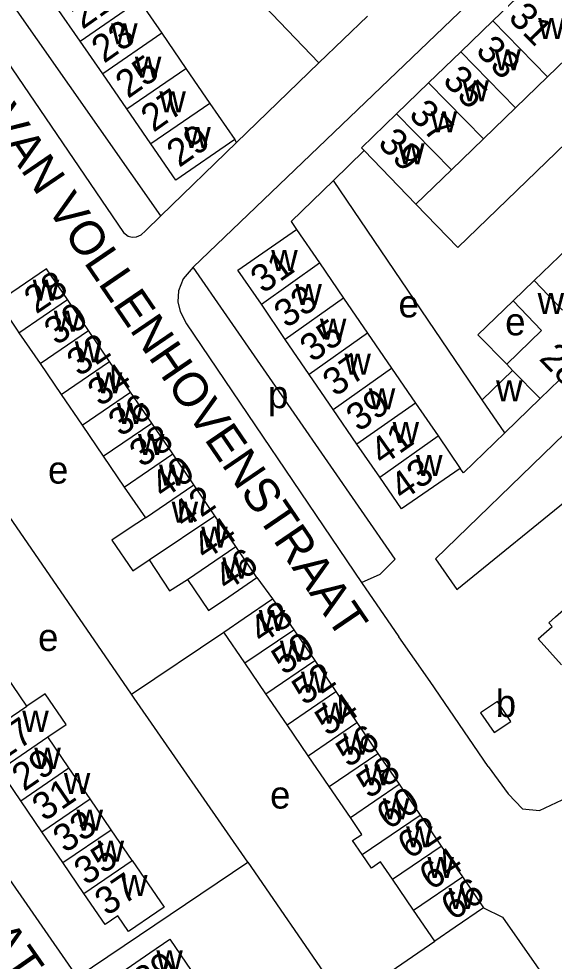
# Model space of a CAD drawing. Extents: x 157569 to 159501, y 382907 to 384670.
# Drawn here: x 158245.2 to 158323.4, y 383803.3 to 383940.8 of the extents above; entities that cross this region are included whole.
import ezdxf

# ---------------------------------------------------------------- set-up
doc = ezdxf.new("R2010")
doc.units = 0
for name, color, linetype in [('BLT_Basislijn', 7, 'Continuous'), ('BLT_Bebouwing', 7, 'Continuous'), ('BLT_Centroide', 7, 'Continuous'), ('BLT_Huisnummer', 7, 'Continuous'), ('BLT_Huisnummer_ tussenligend', 7, 'Continuous'), ('BLT_Onderverdeling_panden', 7, 'Continuous'), ('BLT_Straatnaam', 7, 'Continuous')]:
    doc.layers.add(name, color=color, linetype=linetype)

msp = doc.modelspace()

# ---------------------------------------------------------------- linework, layer by layer
at = {"layer": 'BLT_Basislijn'}
for p, q in [((158265.95, 383912.08), (158220.5, 383977.05)), ((158261.03, 383963.65), (158289.03, 383934.4)), ((158359.94, 383956.53), (158309.3, 383907.45)), ((158270.69, 383904.61), (158313.18, 383945.33)), ((158296.12, 383941.25), (158289.03, 383934.4)), ((158277.01, 383922.81), (158265.95, 383912.08)), ((158291.14, 383917.27), (158295.65, 383921.61)), ((158312.85, 383885.25), (158291.14, 383917.27)), ((158333.76, 383915.53), (158320.42, 383902.64)), ((158309.3, 383907.45), (158303.17, 383913.81)), ((158265.95, 383912.08), (158263.72, 383909.92)), ((158317.36, 383899.68), (158312.24, 383894.74)), ((158312.24, 383894.74), (158316.43, 383890.44)), ((158309.18, 383857.56), (158347.25, 383888.59)), ((158261.67, 383842.28), (158243.3, 383869.04)), ((158279.99, 383859.32), (158282.27, 383856.2)), ((158295.25, 383858.59), (158300.69, 383850.64)), ((158261.67, 383842.28), (158275.15, 383851.34)), ((158305.27, 383844.14), (158300.69, 383850.64)), ((158313.75, 383831.7), (158305.27, 383844.14)), ((158318.74, 383825.56), (158316.63, 383827.74)), ((158253.74, 383800.97), (158278.65, 383817.74)), ((158278.65, 383817.74), (158292.79, 383797.22)), ((158292.79, 383797.22), (158305.93, 383806.23))]:
    msp.add_line(p, q, dxfattribs=at)
for points in [[(158220.5, 383977.05), (158218.89, 383974.99), (158218.63, 383973.43), (158218.85, 383971.66), (158219.87, 383969.38), (158260.5, 383909.68), (158261.19, 383909.11), (158261.77, 383908.99), (158262.42, 383909.01), (158263.1, 383909.3), (158263.72, 383909.92)], [(158289.03, 383934.4), (158277.01, 383922.81)], [(158277.01, 383922.81), (158276.74, 383923.21)], [(158291.14, 383917.27), (158284.96, 383911.28), (158285.76, 383910.11)], [(158270.69, 383904.61), (158269.21, 383902.92), (158268.52, 383901.17), (158268.45, 383899.56), (158268.76, 383898.11), (158269.7, 383896.32), (158295.25, 383858.59)], [(158295.25, 383858.59), (158297.99, 383859.79), (158300.14, 383861.97), (158270.69, 383904.61)], [(158340.56, 383895.5), (158306.05, 383862.05), (158309.18, 383857.56)], [(158316.15, 383880.43), (158310.11, 383874.57), (158309.66, 383875.23)], [(158318.74, 383825.56), (158321.24, 383825.28), (158324.51, 383826.85), (158332.42, 383833.63), (158365.06, 383863.02)], [(158218.79, 383851.78), (158230.42, 383834.52), (158253.74, 383800.97)], [(158278.65, 383817.74), (158262.08, 383841.69), (158261.67, 383842.28)], [(158313.75, 383831.7), (158316.63, 383827.74)], [(158313.04, 383811.09), (158315.83, 383809.75), (158323.28, 383799.09)]]:
    msp.add_lwpolyline(points, dxfattribs=at)
at = {"layer": 'BLT_Bebouwing'}
for p, q in [((158314.39, 383940.55), (158318.93, 383944.94)), ((158262.81, 383943.51), (158266.09, 383938.73)), ((158254.2, 383937.59), (158250.71, 383942.57)), ((158309.72, 383936.03), (158314.39, 383940.55)), ((158266.09, 383938.73), (158269.6, 383933.62)), ((158257.5, 383932.82), (158254.2, 383937.59)), ((158328.48, 383938.27), (158322.39, 383932.38)), ((158305.04, 383931.51), (158309.72, 383936.03)), ((158269.6, 383933.62), (158273.11, 383928.51)), ((158261.01, 383927.71), (158257.5, 383932.82)), ((158322.39, 383932.38), (158317.72, 383927.86)), ((158300.37, 383927), (158305.04, 383931.51)), ((158264.51, 383922.6), (158261.01, 383927.71)), ((158273.11, 383928.51), (158276.74, 383923.21)), ((158317.72, 383927.86), (158313.04, 383923.35)), ((158268.15, 383917.31), (158264.51, 383922.6)), ((158276.74, 383923.21), (158268.15, 383917.31)), ((158313.04, 383923.35), (158308.37, 383918.83)), ((158303.17, 383913.81), (158295.65, 383921.61)), ((158308.37, 383918.83), (158303.17, 383913.81)), ((158277.17, 383904.15), (158285.76, 383910.11)), ((158285.76, 383910.11), (158289.12, 383905.21)), ((158289.12, 383905.21), (158292.63, 383900.09)), ((158280.63, 383899.21), (158277.17, 383904.15)), ((158317.36, 383899.68), (158320.42, 383902.64)), ((158320.42, 383902.64), (158324.59, 383898.34)), ((158255.4, 383895.36), (158252.33, 383899.86)), ((158284.09, 383894.06), (158280.63, 383899.21)), ((158292.63, 383900.09), (158296.13, 383894.97)), ((158321.53, 383895.37), (158317.36, 383899.68)), ((158245.25, 383895.04), (158248.33, 383890.53)), ((158258.48, 383890.85), (158255.4, 383895.36)), ((158296.13, 383894.97), (158299.63, 383889.86)), ((158316.43, 383890.44), (158321.53, 383895.37)), ((158287.59, 383888.94), (158284.09, 383894.06)), ((158248.33, 383890.53), (158251.4, 383886.03)), ((158261.55, 383886.35), (158258.48, 383890.85)), ((158299.63, 383889.86), (158303.14, 383884.74)), ((158312.85, 383885.25), (158317.29, 383889.54)), ((158317.29, 383889.54), (158316.43, 383890.44)), ((158291.11, 383883.84), (158287.59, 383888.94)), ((158324.15, 383888.18), (158321.3, 383885.42)), ((158251.4, 383886.03), (158254.48, 383881.52)), ((158264.62, 383881.84), (158261.55, 383886.35)), ((158316.15, 383880.43), (158312.85, 383885.25)), ((158321.3, 383885.42), (158316.15, 383880.43)), ((158294.58, 383878.79), (158291.11, 383883.84)), ((158303.14, 383884.74), (158306.42, 383879.96)), ((158254.48, 383881.52), (158257.55, 383877.02)), ((158267.7, 383877.34), (158264.62, 383881.84)), ((158306.42, 383879.96), (158309.66, 383875.23)), ((158297.9, 383873.95), (158294.58, 383878.79)), ((158257.55, 383877.02), (158260.62, 383872.51)), ((158270.77, 383872.83), (158267.7, 383877.34)), ((158309.66, 383875.23), (158301.07, 383869.34)), ((158273.85, 383868.33), (158270.77, 383872.83)), ((158301.07, 383869.34), (158297.9, 383873.95)), ((158260.62, 383872.51), (158263.7, 383868.01)), ((158276.92, 383863.82), (158273.85, 383868.33)), ((158279.99, 383859.32), (158276.92, 383863.82)), ((158282.27, 383856.2), (158285.35, 383851.68)), ((158278.23, 383846.83), (158275.15, 383851.34)), ((158285.35, 383851.68), (158288.42, 383847.18)), ((158321.05, 383850.36), (158324.42, 383846.54)), ((158281.3, 383842.32), (158278.23, 383846.83)), ((158288.42, 383847.18), (158291.5, 383842.66)), ((158246.39, 383840.54), (158243.32, 383845.05)), ((158291.5, 383842.66), (158294.58, 383838.15)), ((158284.38, 383837.81), (158281.3, 383842.32)), ((158287.46, 383833.3), (158284.38, 383837.81)), ((158294.58, 383838.15), (158297.65, 383833.64)), ((158252.55, 383831.52), (158249.47, 383836.03)), ((158290.54, 383828.79), (158287.46, 383833.3)), ((158297.65, 383833.64), (158300.73, 383829.13)), ((158245.51, 383826.72), (158242.43, 383831.23)), ((158293.62, 383824.28), (158290.54, 383828.79)), ((158300.73, 383829.13), (158303.81, 383824.62)), ((158248.59, 383822.2), (158245.51, 383826.72)), ((158258.7, 383822.49), (158255.63, 383827)), ((158303.81, 383824.62), (158306.89, 383820.11)), ((158251.67, 383817.69), (158248.59, 383822.2)), ((158261.78, 383817.98), (158258.7, 383822.49)), ((158306.89, 383820.11), (158309.96, 383815.6)), ((158254.74, 383813.18), (158251.67, 383817.69)), ((158302.85, 383810.75), (158299.77, 383815.26)), ((158309.96, 383815.6), (158313.04, 383811.09)), ((158305.93, 383806.23), (158302.85, 383810.75))]:
    msp.add_line(p, q, dxfattribs=at)
for points in [[(158295.65, 383921.61), (158295.24, 383922.04), (158300.37, 383927)], [(158252.33, 383899.86), (158249.25, 383904.37), (158242.18, 383899.54)], [(158242.18, 383899.54), (158245, 383895.41), (158245.25, 383895.04)], [(158321.05, 383850.36), (158323.07, 383852.14), (158322.58, 383852.7), (158323.57, 383853.57), (158349.57, 383876.4), (158353.24, 383872.18), (158353.54, 383872.43)], [(158263.7, 383868.01), (158261.19, 383866.36), (158258.82, 383864.74), (158261.88, 383860.26), (158264.25, 383861.88)], [(158264.25, 383861.88), (158267.22, 383857.35), (158269.85, 383859)], [(158269.85, 383859), (158272.92, 383854.49), (158275.87, 383856.5), (158279.99, 383859.32)], [(158275.15, 383851.34), (158278.14, 383853.38), (158282.27, 383856.2)], [(158249.47, 383836.03), (158252.13, 383837.84), (158249.07, 383842.33), (158246.39, 383840.54)], [(158255.63, 383827), (158252.55, 383831.52)], [(158295.32, 383818.9), (158293.95, 383820.91), (158295.29, 383821.82), (158293.62, 383824.28)], [(158261.78, 383817.98), (158266.42, 383811.17), (158265.39, 383810.47), (158261.26, 383807.65), (158259.7, 383809.94), (158257.82, 383808.66), (158254.74, 383813.18)], [(158299.77, 383815.26), (158298.03, 383817.8), (158296.69, 383816.89), (158295.32, 383818.9)], [(158313.04, 383811.09), (158308.92, 383808.27), (158305.93, 383806.23)], [(158263.35, 383797.15), (158260.24, 383801.71), (158264.37, 383804.53), (158267.27, 383806.51), (158270.38, 383801.95)]]:
    msp.add_lwpolyline(points, dxfattribs=at)
msp.add_lwpolyline([(158315.07, 383841.23), (158312.62, 383839.57), (158314.61, 383836.66), (158317.04, 383838.31)], close=True, dxfattribs=at)
at = {"layer": 'BLT_Onderverdeling_panden'}
for p, q in [((158254.2, 383937.59), (158262.81, 383943.51)), ((158314.39, 383940.55), (158322.39, 383932.38)), ((158266.09, 383938.73), (158257.5, 383932.82)), ((158317.72, 383927.86), (158309.72, 383936.03)), ((158261.01, 383927.71), (158269.6, 383933.62)), ((158305.04, 383931.51), (158313.04, 383923.35)), ((158273.11, 383928.51), (158264.51, 383922.6)), ((158308.37, 383918.83), (158300.37, 383927)), ((158280.63, 383899.21), (158289.12, 383905.21)), ((158245.25, 383895.04), (158252.33, 383899.86)), ((158292.63, 383900.09), (158284.09, 383894.06)), ((158248.33, 383890.53), (158255.4, 383895.36)), ((158296.13, 383894.97), (158287.59, 383888.94)), ((158251.4, 383886.03), (158258.48, 383890.85)), ((158291.11, 383883.84), (158299.63, 383889.86)), ((158317.29, 383889.54), (158321.3, 383885.42)), ((158254.48, 383881.52), (158261.55, 383886.35)), ((158303.14, 383884.74), (158294.58, 383878.79)), ((158257.55, 383877.02), (158264.62, 383881.84)), ((158297.9, 383873.95), (158306.42, 383879.96)), ((158260.62, 383872.51), (158267.7, 383877.34)), ((158263.7, 383868.01), (158270.77, 383872.83)), ((158264.25, 383861.88), (158273.85, 383868.33)), ((158269.85, 383859), (158276.92, 383863.82)), ((158278.23, 383846.83), (158285.35, 383851.68)), ((158281.3, 383842.32), (158288.42, 383847.18)), ((158284.38, 383837.81), (158291.5, 383842.66)), ((158239.36, 383835.74), (158246.39, 383840.54)), ((158287.46, 383833.3), (158294.58, 383838.15)), ((158242.43, 383831.23), (158249.47, 383836.03)), ((158290.54, 383828.79), (158297.65, 383833.64)), ((158245.51, 383826.72), (158252.55, 383831.52)), ((158293.62, 383824.28), (158300.73, 383829.13)), ((158248.59, 383822.2), (158255.63, 383827)), ((158295.32, 383818.9), (158303.81, 383824.62)), ((158251.67, 383817.69), (158258.7, 383822.49)), ((158299.77, 383815.26), (158306.89, 383820.11)), ((158254.74, 383813.18), (158261.78, 383817.98)), ((158302.85, 383810.75), (158309.96, 383815.6))]:
    msp.add_line(p, q, dxfattribs=at)

# ---------------------------------------------------------------- texts
at = {"layer": 'BLT_Centroide'}
for s, p in [('w', (158258.7, 383937.12)), ('w', (158321.03, 383937.88)), ('w', (158314.64, 383933.34)), ('w', (158262.17, 383932.25)), ('w', (158309.98, 383928.81)), ('w', (158265.74, 383927.19)), ('w', (158305.34, 383924.27)), ('w', (158269.38, 383922)), ('w', (158300.59, 383919.62)), ('w', (158282.07, 383904.03)), ('w', (158247.26, 383899.69)), ('w', (158285.59, 383899.06)), ('e', (158300.64, 383897.27)), ('w', (158320.95, 383897.76)), ('w', (158250.33, 383895.19)), ('e', (158316.21, 383894.65)), ('w', (158289.17, 383894)), ('w', (158253.4, 383890.69)), ('w', (158292.75, 383888.91)), ('w', (158256.48, 383886.19)), ('w', (158314.88, 383885.01)), ('p', (158281.6, 383884.02)), ('w', (158296.31, 383883.84)), ('w', (158259.55, 383881.69)), ('w', (158299.78, 383878.94)), ('w', (158262.62, 383877.19)), ('w', (158303.2, 383874.12)), ('e', (158249.49, 383873.01)), ('w', (158265.7, 383872.69)), ('w', (158267.53, 383867.31)), ('w', (158271.85, 383863.66)), ('w', (158274.92, 383859.16)), ('w', (158280.25, 383851.5)), ('e', (158248.04, 383848.58)), ('w', (158283.33, 383847)), ('w', (158286.41, 383842.5)), ('b', (158314.83, 383838.94)), ('w', (158289.48, 383837.97)), ('w', (158245.73, 383836.78)), ('w', (158292.56, 383833.47)), ('w', (158247.49, 383831.38)), ('w', (158295.64, 383828.97)), ('w', (158251.8, 383827.72)), ('e', (158281.9, 383825.58)), ('w', (158298.35, 383824)), ('w', (158253.65, 383822.34)), ('w', (158301.75, 383819.94)), ('w', (158256.73, 383817.84)), ('w', (158304.87, 383815.44)), ('w', (158260.15, 383812.81)), ('w', (158307.95, 383810.91)), ('w', (158265.3, 383801.84))]:
    msp.add_text(s, height=4, dxfattribs=at).set_placement(p)
at = {"layer": 'BLT_Huisnummer'}
for s, rotation, p in [('21', 35.2169, (158254.52, 383939.22)), ('31', 314.2979, (158316.51, 383940.89)), ('25', 35.2169, (158261.17, 383929.13)), ('35', 314.2979, (158306.94, 383931.68)), ('29', 35.2169, (158268.64, 383919.06)), ('39', 314.2979, (158297.47, 383922.55)), ('31', 35.2169, (158280.88, 383900.65)), ('28', 34.3082, (158247.77, 383897.68)), ('35', 35.2169, (158288.08, 383890.6)), ('32', 34.3082, (158254.02, 383888.53)), ('28', 314.1628, (158321.02, 383891.16)), ('39', 35.2169, (158294.83, 383880.47)), ('36', 34.3082, (158260.08, 383879.75)), ('40', 34.3082, (158266.28, 383870.68)), ('43', 35.2169, (158301.24, 383870.4)), ('46', 34.3082, (158275.56, 383857.21)), ('48', 34.3082, (158280.66, 383849.51)), ('52', 34.3082, (158286.88, 383840.53)), ('27', 34.2927, (158242.8, 383832.48)), ('56', 34.3082, (158293.29, 383831.47)), ('31', 34.2927, (158248.95, 383823.61)), ('60', 34.3082, (158299.19, 383822.38)), ('37', 34.2927, (158258.09, 383809.81)), ('66', 34.3082, (158308.61, 383809.11)), ('39', 34.2932, (158263.73, 383798.33))]:
    msp.add_text(s, height=4, rotation=rotation, dxfattribs=at).set_placement(p)
at = {"layer": 'BLT_Huisnummer_ tussenligend'}
for s, rotation, p in [('23', 35.2169, (158257.67, 383934.27)), ('33', 314.2979, (158311.75, 383936.04)), ('27', 35.2169, (158264.88, 383924.2)), ('37', 314.2979, (158301.99, 383926.72)), ('33', 35.2169, (158284.31, 383895.59)), ('30', 34.3082, (158250.71, 383893.08)), ('37', 35.2169, (158291.42, 383885.59)), ('34', 34.3082, (158257.07, 383884.16)), ('38', 34.3082, (158263.16, 383875.27)), ('41', 35.2169, (158298.31, 383875.53)), ('42', 34.3082, (158269.36, 383866.32)), ('44', 34.3082, (158272.42, 383861.71)), ('50', 34.3082, (158283.9, 383844.96)), ('54', 34.3082, (158290.23, 383836.04)), ('29', 34.2927, (158245.99, 383828)), ('58', 34.3082, (158296.31, 383826.93)), ('33', 34.2927, (158251.99, 383818.99)), ('62', 34.3082, (158302.27, 383818.08)), ('35', 34.2927, (158255.06, 383814.27)), ('64', 34.3082, (158305.44, 383813.53))]:
    msp.add_text(s, height=4, rotation=rotation, dxfattribs=at).set_placement(p)
at = {"layer": 'BLT_Straatnaam'}
for s, rotation, p in [('VAN VOLLENHOVENSTRAAT', 304.282, (158240.39, 383926.18)), ('VAN DER MARCKSTRAAT', 304.7861, (158198.15, 383867.24))]:
    msp.add_text(s, height=5, rotation=rotation, dxfattribs=at).set_placement(p)

doc.saveas('drawing.dxf')
